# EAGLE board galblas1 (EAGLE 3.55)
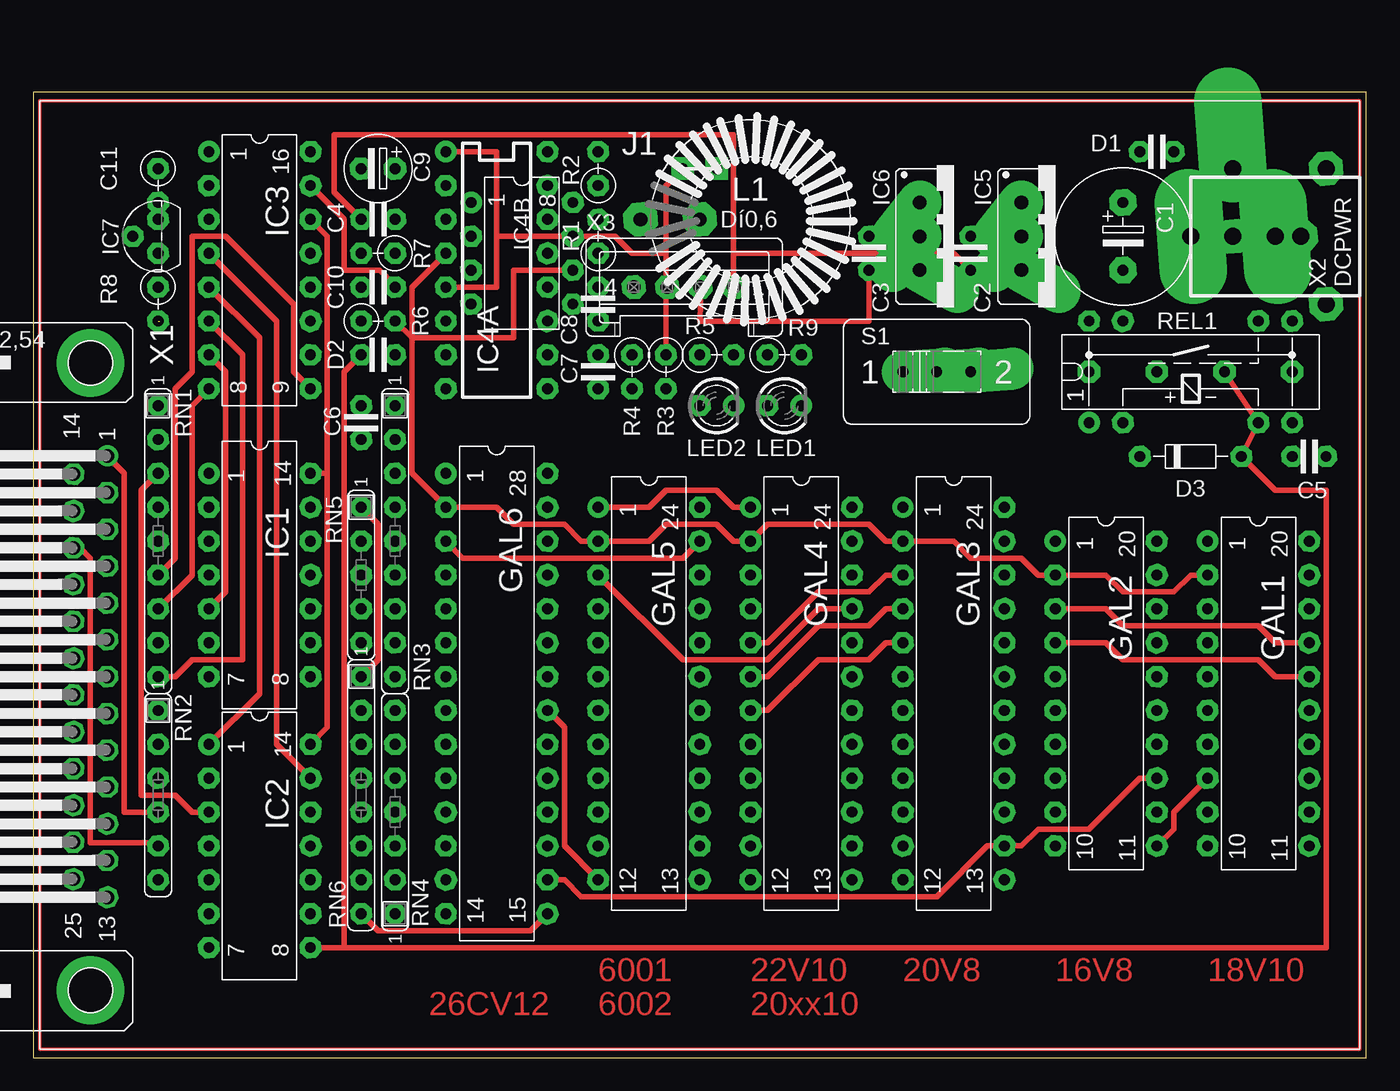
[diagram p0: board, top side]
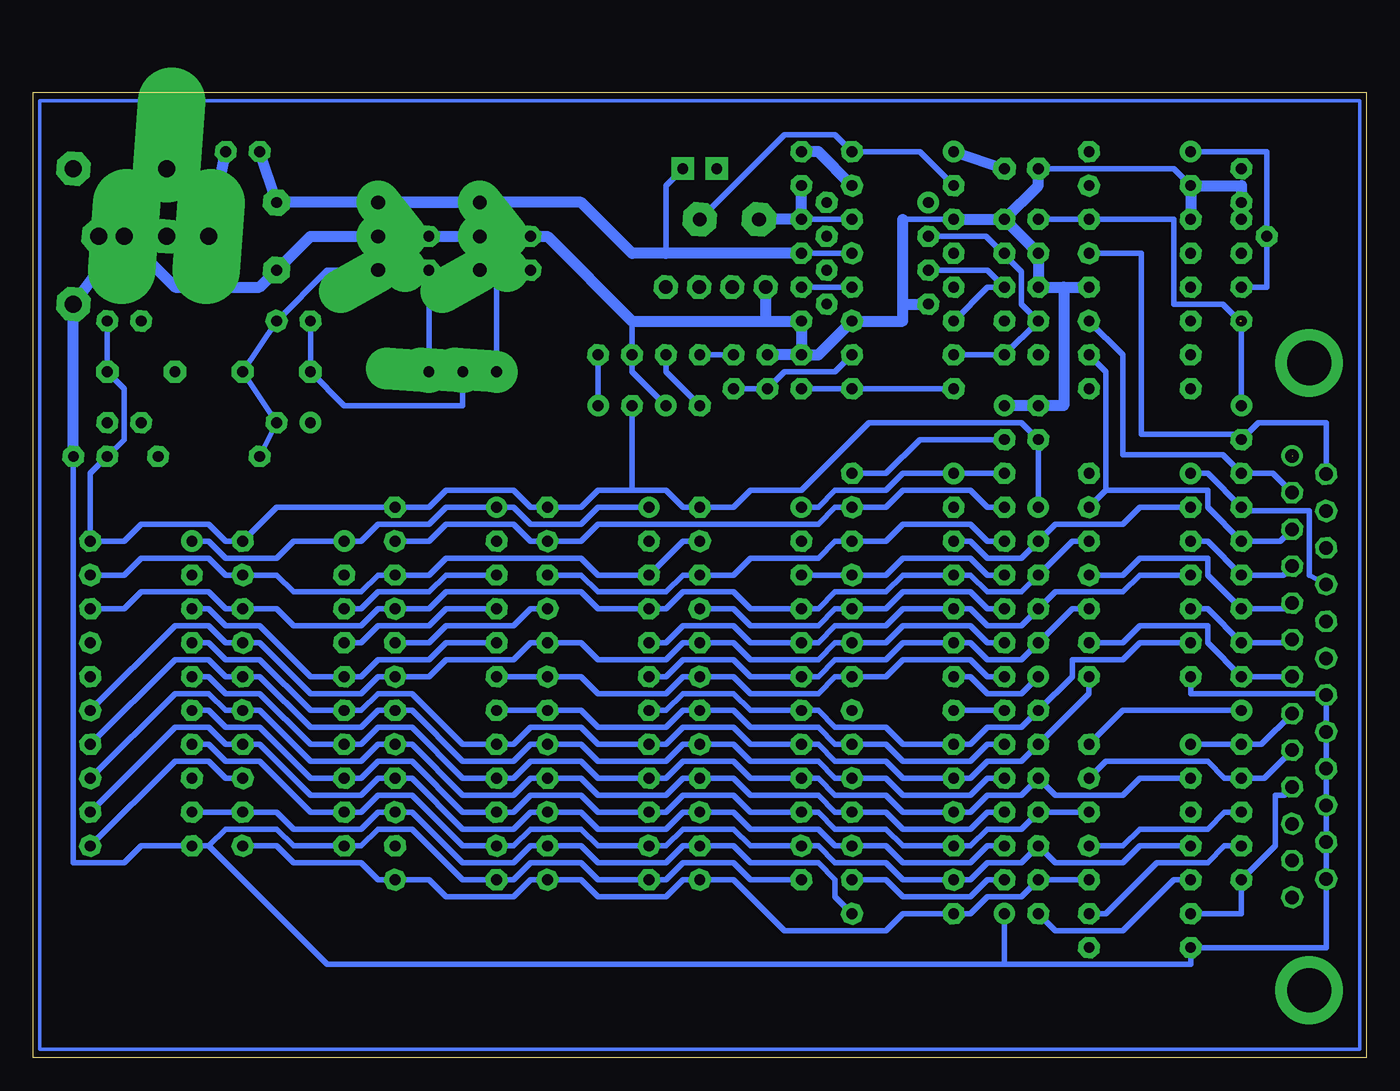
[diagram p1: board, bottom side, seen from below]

Size 100 x 72.38 mm. Coordinates in mm from the lower left corner, seen from the top.
Outline: 0,0 100,0 100,72.38 0,72.38 0,0
Copper layers used: Top, Bottom

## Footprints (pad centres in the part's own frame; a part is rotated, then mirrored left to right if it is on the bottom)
-5 = drill 0.813 pad 2.007 octagon:  -2.54,0;  2.54,0
2,5 = drill 0.813 pad 1.6 octagon:  -1.27,0;  1.27,0
-2,5L = drill 0.813 pad 1.676 octagon:  0,0;  2.54,0
-2,5 = drill 0.813 pad 1.6 octagon:  0,0;  2.54,0
7,5 = drill 0.813 pad 1.6 octagon:  -3.81,0;  3.81,0
L20 = drill 0.813 pad 1.6 round:  -11.43,-3.81 | drill 0.813 pad 1.6 octagon:  -8.89,-3.81;  -6.35,-3.81;  -3.81,-3.81;  -1.27,-3.81;  1.27,-3.81;  3.81,-3.81;  6.35,-3.81;  8.89,-3.81;  11.43,-3.81;  11.43,3.81;  8.89,3.81;  6.35,3.81;  3.81,3.81;  1.27,3.81;  -1.27,3.81;  -3.81,3.81;  -6.35,3.81;  -8.89,3.81;  -11.43,3.81
L24-3 = drill 0.813 pad 1.6 round:  -13.97,-3.81 | drill 0.813 pad 1.6 octagon:  -11.43,-3.81;  -8.89,-3.81;  -6.35,-3.81;  -3.81,-3.81;  -1.27,-3.81;  1.27,-3.81;  3.81,-3.81;  6.35,-3.81;  8.89,-3.81;  11.43,-3.81;  13.97,-3.81;  13.97,3.81;  11.43,3.81;  8.89,3.81;  6.35,3.81;  3.81,3.81;  1.27,3.81;  -1.27,3.81;  -3.81,3.81;  -6.35,3.81;  -8.89,3.81;  -11.43,3.81;  -13.97,3.81
L28-3 = drill 0.813 pad 1.6 round:  -16.51,-3.81 | drill 0.813 pad 1.6 octagon:  -13.97,-3.81;  -11.43,-3.81;  -8.89,-3.81;  -6.35,-3.81;  -3.81,-3.81;  -1.27,-3.81;  1.27,-3.81;  3.81,-3.81;  6.35,-3.81;  8.89,-3.81;  11.43,-3.81;  13.97,-3.81;  16.51,-3.81;  16.51,3.81;  13.97,3.81;  11.43,3.81;  8.89,3.81;  6.35,3.81;  3.81,3.81;  1.27,3.81;  -1.27,3.81;  -3.81,3.81;  -6.35,3.81;  -8.89,3.81;  -11.43,3.81;  -13.97,3.81;  -16.51,3.81
L14 = drill 0.813 pad 1.6 round:  -7.62,-3.81 | drill 0.813 pad 1.6 octagon:  -5.08,-3.81;  -2.54,-3.81;  0,-3.81;  2.54,-3.81;  5.08,-3.81;  7.62,-3.81;  7.62,3.81;  5.08,3.81;  2.54,3.81;  0,3.81;  -2.54,3.81;  -5.08,3.81;  -7.62,3.81
L16 = drill 0.813 pad 1.6 round:  -8.89,-3.81 | drill 0.813 pad 1.6 octagon:  -6.35,-3.81;  -3.81,-3.81;  -1.27,-3.81;  1.27,-3.81;  3.81,-3.81;  6.35,-3.81;  8.89,-3.81;  8.89,3.81;  6.35,3.81;  3.81,3.81;  1.27,3.81;  -1.27,3.81;  -3.81,3.81;  -6.35,3.81;  -8.89,3.81
L16' = drill 0.813 pad 1.6 round:  -8.89,-3.81 | drill 0.813 pad 1.6 octagon:  -6.35,-3.81;  -1.27,-3.81;  -3.81,-3.81;  1.27,-3.81;  3.81,-3.81;  6.35,-3.81;  8.89,-3.81;  8.89,3.81;  6.35,3.81;  3.81,3.81;  1.27,3.81;  -1.27,3.81;  -3.81,3.81;  -6.35,3.81;  -8.89,3.81
L08 = drill 0.813 pad 1.6 round:  -3.81,-3.81 | drill 0.813 pad 1.6 octagon:  -1.27,-3.81;  1.27,-3.81;  3.81,-3.81;  3.81,3.81;  1.27,3.81;  -1.27,3.81;  -3.81,3.81
XXS = drill 1.016 pad 3.251 offset:  -2.54,-2.54;  0,-2.54;  2.54,-2.54
92 = drill 0.813 pad 1.6 octagon:  -1.27,0;  0,1.905;  1.27,0
16 = drill 1.016 pad 2.54 octagon:  -3.81,0;  -8.255,0
D3 = drill 0.813 pad 1.6 octagon:  -1.27,0 | drill 0.813 pad 1.6 round:  1.27,0
1A = drill 0.813 pad 1.6 round:  -7.62,-3.81 | drill 0.813 pad 1.6 octagon:  -5.08,-3.81;  5.08,-3.81;  7.62,-3.81;  7.62,3.81;  5.08,3.81;  -5.08,3.81;  -7.62,3.81
L9 = drill 0.813 pad 1.6 round:  -10.16,0 | drill 0.813 pad 1.6 octagon:  -7.62,0;  -5.08,0;  -2.54,0;  0,0;  2.54,0;  5.08,0;  7.62,0;  10.16,0
L6 = drill 0.813 pad 1.6 round:  -6.35,0 | drill 0.813 pad 1.6 octagon:  -3.81,0;  -1.27,0;  1.27,0;  3.81,0;  6.35,0
L7 = drill 0.813 pad 1.6 round:  -7.62,0 | drill 0.813 pad 1.6 octagon:  -5.08,0;  -2.54,0;  0,0;  2.54,0;  5.08,0;  7.62,0
L5 = drill 0.813 pad 1.6 round:  -5.08,0 | drill 0.813 pad 1.6 octagon:  -2.54,0;  0,0;  2.54,0;  5.08,0
L8 = drill 0.813 pad 1.6 round:  -8.89,0 | drill 0.813 pad 1.6 octagon:  -6.35,0;  -3.81,0;  -1.27,0;  1.27,0;  3.81,0;  6.35,0;  8.89,0
51 = drill 0.813 pad 3.15 offset:  -2.54,0;  0,0;  2.54,0
5HP = drill 1.016 pad 1.6 octagon:  16.561,1.27;  13.792,1.27;  11.049,1.27;  8.28,1.27;  5.512,1.27;  2.769,1.27;  0,1.27;  -2.769,1.27;  -5.512,1.27;  -8.28,1.27;  -11.049,1.27;  -13.792,1.27;  15.189,-1.27;  12.421,-1.27;  9.652,-1.27;  6.909,-1.27;  4.14,-1.27;  1.372,-1.27;  -1.372,-1.27;  -4.14,-1.27;  -6.909,-1.27;  -9.652,-1.27;  -12.421,-1.27;  -15.189,-1.27 | drill 1.016 pad 1.6 round:  -16.561,1.27 | drill 3.302 pad 5.08 round:  -23.52,0;  23.52,0
PWR = drill 1.27 pad 2.54 octagon:  -5.08,-7.62;  5.08,-7.62;  0,-0.635;  0,-5.715 | drill 1.27 pad 5.08 offset:  5.08,-0.635 | drill 1.27 pad 5.08 long:  0,2.54;  0,-3.81
4P = drill 1.016 pad 1.778 octagon:  -4.978,0;  -7.493,0;  -2.489,0;  0,0

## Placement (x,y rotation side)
C1  470u/16V  [-5]  81.75,61.59 270 top
C2  100n  [2,5]  70.32,60.32 270 top
C3  100n  [2,5]  62.7,60.32 270 top
C4  100n  [2,5]  25.87,62.86 180 top
C5  100n  [2,5]  95.72,45.08 180 top
C6  100n  [2,5]  24.6,47.62 270 top
C7  100n  [2,5]  42.38,51.43 90 top
C8  10n  [2,5]  42.38,56.51 270 top
C9  100u/35V  [-2,5L]  27.14,66.67 180 top
C10  4n7  [2,5]  25.87,57.78 180 top
C11  1u/3V  [-2,5]  9.36,66.67 270 top
D1  1N4001  [2,5]  84.29,67.94 180 top
D2  1N4148  [2,5]  25.87,52.7 0 top
D3  1N4148  [7,5]  86.83,45.08 180 top
GAL1  18V10  [L20]  91.91,27.3 270 top
GAL2  16V8  [L20]  80.48,27.3 270 top
GAL3  20V8  [L24-3]  69.05,27.3 270 top
GAL4  22V10/20xx10  [L24-3]  57.62,27.3 270 top
GAL5  6001/6002  [L24-3]  46.19,27.3 270 top
GAL6  26CV12  [L28-3]  34.76,27.3 270 top
IC1  7417  [L14]  16.98,36.19 270 top
IC2  7417  [L14]  16.98,15.87 270 top
IC3  TLC7524JN  [L16]  16.98,59.05 270 top
IC4A  78S40  [L16']  34.76,59.05 270 top
IC4B  CA3140E  [L08]  36.66,60.32 270 top
IC5  7805  [XXS]  76.67,61.59 270 top
IC6  LM3940-3.3  [XXS]  69.05,61.59 270 top
IC7  LM336Z2.5  [92]  9.36,61.59 90 top
L1  470uH  [16]  53.81,62.86 0 top
LED1  LED3YE  [D3]  56.35,48.89 0 top
LED2  LED3GR  [D3]  51.27,48.89 0 top
R1  1R2  [-2,5]  42.38,60.32 90 top
R2  180R  [-2,5]  42.38,65.4 90 top
R3  220k  [-2,5]  47.46,52.7 270 top
R4  12k  [-2,5]  44.92,52.7 270 top
R5  4k7  [-2,5]  50,52.7 0 top
R6  100k  [-2,5]  24.6,55.24 0 top
R7  12k  [-2,5]  27.14,60.32 180 top
R8  390R  [-2,5]  9.36,57.78 270 top
R9  820R  [-2,5]  55.08,52.7 0 top
REL1  RR1A  [1A]  86.83,51.43 0 top
RN1  4k7  [L9]  9.36,38.73 270 top
RN2  4k7  [L6]  9.36,19.68 270 top
RN3  4k7  [L9]  27.14,38.73 270 top
RN4  4k7  [L7]  27.14,18.41 90 top
RN5  4k7  [L5]  24.6,36.19 270 top
RN6  4k7  [L8]  24.6,19.68 270 top
S1  SW1  [51]  67.78,51.43 0 top
X1  M25HP  [5HP]  4.28,28.57 270 top
X2  DCPWR  [PWR]  89.37,61.59 90 top
X3  S04P  [4P]  52.54,57.78 0 top

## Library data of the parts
C1-C11 D1-D3 R1-R9 = DISCRETE
GAL1-GAL6 = DIL
IC1 IC2 = 74XX
IC3 IC4B IC7 = LINEAR
IC4A IC5 IC6 = V-REG
L1 = IND-A
LED1 LED2 = LED
REL1 = RELAIS
RN1-RN6 = R-SIL
S1 = SWITCH
X1 = SUBD-A
X2 = SPECIAL
X3 = CON-MT

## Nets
/ACK: IC2. RN2. X1.
/STB: GAL1. GAL2. GAL3. GAL4. GAL5. GAL6. IC2. RN6.
/STROBE: IC2. RN2. X1.
D0: IC2. IC3. RN1. X1.
D1: IC1. IC3. RN1. X1.
D2: IC1. IC3. RN1. X1.
D3: IC1. IC3. RN1. X1.
D4: IC1. IC3. RN1. X1.
D5: IC1. IC3. RN1. X1.
D6: IC2. IC3. RN2. X1.
D7: IC2. IC3. RN2. X1.
EDIT: GAL1. GAL2. GAL3. GAL4. GAL5. GAL6. IC4A. IC4B. R6.
N$1: IC3. RN1. X1.
N$2: D1. X2.
N$3: IC1. RN1. X1.
N$4: IC2. RN2. X1.
N$5: C7. IC4A.
N$6: LED2. R5.
N$7: C8. IC4A.
N$8: REL1. S1.
N$9: GAL6. RN4.
N$10: GAL3. GAL4. GAL5. GAL6. RN3.
N$11: IC4A. R3. R4.
N$12: LED1. R9.
N$13: IC4A. L1. R1. R2.
N$14: IC4A. R2.
N$15: GAL5. GAL6. RN3.
N$16: GAL1. GAL2. GAL3. GAL4. GAL5. GAL6. RN3.
N$17: IC4A. L1.
N$18: C9. IC4A. IC4B. R3. R5. X3.
N$19: C1. C2. C3. C4. C5. C6. C7. C8. C9. C10. C11. GAL1. GAL2. GAL3. GAL4. GAL5. GAL6. IC1. IC2. IC3. IC4A. IC4B. IC5. IC6. IC7. LED2. R4. R7. R9. RN3. RN4. X1. X2. X3.
N$20: C1. D1. IC4A. IC5. IC6. R1.
N$21: C11. IC3. IC7. R8.
N$22: GAL3. GAL4. GAL5. GAL6. RN3.
N$23: D2. IC4A. IC4B. R6. R7.
N$24: GAL3. GAL4. GAL5. GAL6. RN4.
N$25: GAL1. GAL2. GAL3. GAL4. GAL5. GAL6. RN4.
N$26: GAL1. GAL2. GAL3. GAL4. GAL5. GAL6. RN4.
N$28: GAL1. GAL2. GAL3. GAL4. GAL5. GAL6. RN4.
N$29: GAL1. GAL2. GAL3. GAL6. RN4.
N$30: GAL6. RN3.
N$31: GAL1. GAL2. GAL3. GAL4. GAL5. GAL6. RN3.
N$32: GAL4. GAL5. GAL6. RN3.
N$33: GAL3. GAL4. GAL6. RN3.
N$35: C10. IC3. IC4A. IC4B.
N$36: C2. C4. D3. IC1. IC2. IC3. IC5. R8. REL1. RN1. RN2. S1. X3.
N$39: D2. D3. IC2. REL1.
P/V: GAL1. GAL2. GAL3. GAL4. GAL5. GAL6. IC1. RN5.
RA0: GAL1. GAL2. GAL3. GAL4. GAL5. GAL6. IC1. RN5.
RA1: GAL1. GAL2. GAL3. GAL4. GAL5. GAL6. IC1. RN5.
RA2: GAL1. GAL2. GAL3. GAL4. GAL5. GAL6. IC1. RN5.
RA3: GAL1. GAL2. GAL3. GAL4. GAL5. GAL6. IC1. RN6.
RA4: GAL1. GAL2. GAL3. GAL4. GAL5. GAL6. IC1. RN6.
RA5: GAL1. GAL2. GAL3. GAL4. GAL5. GAL6. IC2. RN6.
SCHALT: X2.
SCLK: GAL1. GAL2. GAL3. GAL4. GAL5. GAL6. IC2. RN6.
SDIN: GAL1. GAL2. GAL3. GAL4. GAL5. GAL6. IC2. RN6.
SDOUT: GAL1. GAL2. GAL3. GAL4. GAL5. GAL6. IC2. RN6.
SW1: C3. IC6. S1. X3.
VCC: C5. C6. GAL1. GAL2. GAL3. GAL4. GAL5. GAL6. LED1. REL1. RN5. RN6.

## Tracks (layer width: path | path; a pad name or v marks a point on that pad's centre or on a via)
/ACK
  Bottom 0.406: 5.55,20.29 6.16,19.68 6.82,19.68 6.82,15.87 RN2. 9.36,10.79 13.17,10.79
/STB
  Top 0.406: 88.1,20.95 85.56,18.41 85.56,17.14 84.29,15.87
  Bottom 0.406: 84.29,15.87 81.75,15.87 80.48,14.6 75.4,14.6 74.13,13.33 72.86,13.33 70.32,13.33 69.05,12.06 63.97,12.06 62.7,13.33 61.43,13.33 58.89,13.33 57.62,12.06 52.54,12.06 51.27,13.33 50,13.33 47.46,13.33 43.65,9.52 36.03,9.52 34.76,10.79 30.95,10.79 29.68,10.79 28.41,12.06 25.87,12.06 24.6,13.33 20.79,13.33
/STROBE  (1 unrouted)
  Top 0.406: 5.55,45.08 6.82,43.81 6.82,18.41 9.36,18.41
  Bottom 0.406: 9.36,18.41 10.63,18.41 11.9,17.14 16.98,17.14 18.25,15.87 20.79,15.87
D0
  Top 0.406: 9.36,43.81 8.09,42.54 8.09,19.68 10.63,19.68 11.9,18.41 13.17,18.41
  Bottom 0.406: 5.55,42.36 7,43.81 9.36,43.81 10.76,45.21 18.25,45.21 18.25,52.7 20.79,55.24
D1
  Bottom 0.406: 5.55,39.62 6.44,38.73 9.36,38.73 11.9,41.27 11.9,42.54 19.52,42.54 | 19.52,42.54 20.79,41.27 | 19.52,42.54 19.52,51.43 20.79,52.7
D2
  Top 0.406: 20.79,50.16 19.52,51.43 19.52,56.51 14.44,61.59 11.9,61.59 11.9,51.43 10.63,50.16 10.63,37.46 9.36,36.19
  Bottom 0.406: 5.55,36.85 6.21,36.19 9.36,36.19 11.9,38.73 13.17,38.73
D3
  Top 0.406: 13.17,50.16 11.9,48.89 11.9,36.19 9.36,33.65
  Bottom 0.406: 5.55,34.08 5.98,33.65 9.36,33.65 11.9,36.19 11.9,37.46 16.98,37.46 18.25,36.19 20.79,36.19
D4
  Top 0.406: 13.17,52.7 14.44,51.43 14.44,34.92 13.17,33.65
  Bottom 0.406: 5.55,31.34 5.78,31.11 9.36,31.11 11.9,33.65 13.17,33.65
D5
  Top 0.406: 13.17,55.24 15.71,52.7 15.71,29.84 11.9,29.84 10.63,28.57 RN1.
  Bottom 0.406: 5.55,28.57 RN1. 11.9,31.11 11.9,32.38 16.98,32.38 18.25,31.11 20.79,31.11
D6
  Top 0.406: 13.17,57.78 16.98,53.97 16.98,27.3 13.17,23.49
  Bottom 0.406: 5.55,25.8 7.86,23.49 9.36,23.49 13.17,23.49
D7
  Top 0.406: 13.17,60.32 18.25,55.24 18.25,23.49 20.79,20.95
  Bottom 0.406: 5.55,23.06 7.66,20.95 9.36,20.95 10.63,20.95 11.9,22.22 19.52,22.22 20.79,20.95
EDIT
  Top 0.406: 88.1,36.19 86.83,36.19 85.56,34.92 81.75,34.92 80.48,36.19 76.67,36.19 75.4,36.19 74.13,37.46 70.32,37.46 69.05,38.73 65.24,38.73 63.97,38.73 62.7,40 55.08,40 53.81,38.73 52.54,38.73 51.27,40 47.46,40 46.19,38.73 42.38,38.73 41.11,38.73 39.84,40 36.03,40 34.76,41.27 30.95,41.27 28.41,43.81 28.41,53.97 | 40.48,59.05 36.03,59.05 36.03,53.97 28.41,53.97 | 28.41,53.97 R6. | 30.95,60.32 28.41,57.78 28.41,53.97
N$1
  Bottom 0.406: 3.01,43.76 3.01,47.62 8.09,47.62 9.36,46.35 9.74,46.73 16.85,46.73 16.85,60.32 20.79,60.32
N$2
  Bottom 0.813: 85.56,67.94 86.83,61.59 89.37,61.59
N$3
  Bottom 0.406: 3.01,35.48 4.28,36.19 4.28,41.02 9.11,41.02 9.36,41.27 11.9,43.81 13.17,43.81
N$4
  Top 0.406: 3.01,38.22 3.52,38.22 4.28,37.46 4.28,16.12 9.11,16.12 9.36,15.87
  Bottom 0.406: 9.36,15.87 10.63,15.87 11.9,14.6 15.71,14.6 19.52,10.79 20.79,10.79
N$5
  Bottom 0.406: 30.95,50.16 38.57,50.16 42.38,50.16
N$6
  Bottom 0.406: 50,48.89 52.54,51.43 R5.
N$7
  Bottom 0.406: 38.57,57.78 42.38,57.78
N$8  (via drill 0.81 pad 1.68)
  Bottom 0.406: 67.78,51.43 67.78,48.89 76.67,48.89 v79.21,51.43 REL1.
N$9
  Bottom 0.406: RN4. 30.95,26.03
N$10
  Top 0.406: 61.43,33.65 58.89,33.65 55.08,29.84 48.73,29.84 42.38,36.19
  Bottom 0.406: 42.38,36.19 38.57,36.19 36.03,36.19 34.76,37.46 29.68,37.46 28.41,36.19 27.14,36.19 | 61.43,33.65 62.7,33.65 63.97,32.38 69.05,32.38 70.32,31.11 72.86,31.11
N$11
  Bottom 0.406: 38.57,52.7 39.84,51.43 43.65,51.43 R4. R3.
N$12
  Bottom 0.406: LED1. R9.
N$13
  Bottom 0.406: 38.57,62.86 R1.
  Bottom 0.813: 42.38,65.4 R1. L1.
N$14
  Bottom 0.813: 38.57,65.4 41.11,67.94 R2.
N$15
  Bottom 0.406: 50,33.65 47.46,33.65 46.19,32.38 41.11,32.38 39.84,33.65 38.57,33.65 36.03,33.65 34.76,34.92 29.68,34.92 28.41,33.65 27.14,33.65
N$16
  Bottom 0.406: 27.14,31.11 28.41,31.11 29.68,32.38 34.76,32.38 36.03,31.11 38.57,31.11 39.84,31.11 41.11,29.84 46.19,29.84 47.46,31.11 50,31.11 51.27,31.11 52.54,29.84 57.62,29.84 58.89,31.11 61.43,31.11 62.7,31.11 63.97,29.84 69.05,29.84 70.32,28.57 72.86,28.57 74.13,28.57 75.4,27.3 79.21,27.3 83.02,31.11 84.29,31.11 85.56,31.11 86.83,32.38 89.37,32.38 95.72,26.03
N$17
  Bottom 0.406: 30.95,65.4 33.49,67.94 IC4A. 39.84,69.21 43.65,69.21 50,62.86
N$18  (via drill 0.81 pad 1.68)
  Top 0.406: 47.46,57.78 47.46,52.7 | 47.46,57.78 47.56,57.78 | 47.46,60.32 47.46,57.78 | 47.46,60.32 44.92,60.32 43.65,61.59 40.48,61.59 34.76,61.59 | 34.76,61.59 34.76,67.94 30.95,67.94 | 47.46,60.32 47.46,65.4 v48.73,66.67 | 30.95,57.78 34.76,57.78 34.76,61.59
  Bottom 0.406: 47.46,52.7 50,52.7
  Bottom 0.813: 30.95,67.94 27.14,66.67
N$19
  Top 0.406: 38.57,26.03 39.84,24.76 39.84,15.87 42.38,13.33
  Bottom 0.406: 42.38,13.33 46.19,13.33 47.46,14.6 51.27,14.6 52.54,13.33 53.81,13.33 57.62,13.33 58.89,14.6 62.7,14.6 63.97,13.33 65.24,13.33 67.78,13.33 71.59,17.14 74.13,17.14 75.4,15.87 76.67,15.87 80.48,15.87 81.75,17.14 85.56,17.14 86.83,15.87 | 24.6,48.89 27.14,48.89 | 86.83,15.87 88.1,15.87 91.91,15.87 93.18,14.6 96.99,14.6 96.99,45.08 | 27.14,6.98 13.17,6.98 13.17,8.25 3.01,8.25 3.01,13.38 3.01,16.15 3.01,18.41 | 13.17,28.57 13.17,27.3 3.01,27.3 3.01,27.2 3.01,24.43 3.01,21.66 | 27.14,6.98 27.14,10.79 | 27.14,6.98 77.94,6.98 86.83,15.87 | 34.76,62.86 30.95,62.86 | 55.08,55.24 55.08,52.7 55.08,51.43 LED2. | 3.01,18.41 3.01,18.92 3.01,20.95 | 3.01,21.66 3.01,22.22 | 3.01,20.95 3.01,21.66 | 3.01,18.41 3.01,20.95 | 3.01,18.41 3.01,21.66 | 13.17,65.4 14.44,66.67 C9. | C8. C7. C8.
  Bottom 0.813: 70.32,61.59 62.7,61.59 66.51,61.59 70.32,61.59 | 70.32,61.59 74.13,61.59 70.32,61.59 | 70.32,61.59 79.21,61.59 C1. 83.02,57.78 89.37,57.78 93.18,61.59 96.99,56.51 96.99,45.08 | C7. 41.11,52.7 38.57,55.24 34.76,55.24 34.76,56.51 | 34.76,56.51 34.76,62.86 | C7. C8. 44.92,55.24 | C7. 44.92,52.7 | 27.14,48.89 24.6,48.89 22.7,48.89 22.7,57.78 | 70.32,61.59 61.43,61.59 55.08,55.24 44.92,55.24 | 45.05,57.78 45.05,55.37 44.92,55.24 | 13.17,62.86 13.17,65.4 9.36,65.4 IC7. | 34.76,56.51 32.85,56.51 | 30.95,62.86 27.14,62.86 | 22.7,57.78 C10. R7. 27.14,62.86 | 27.14,62.86 24.6,65.4 C9. | 22.7,57.78 20.79,57.78
N$20  (via drill 0.81 pad 1.68)
  Bottom 0.406: 38.57,60.32 42.38,60.32 | 52.54,60.32 52.54,65.4 v51.27,66.67
  Bottom 0.813: 42.38,60.32 52.54,60.32 55.08,60.32 58.89,64.13 74.13,64.13 66.51,64.13 81.75,64.13 D1.
N$21
  Bottom 0.406: 13.17,67.94 9.36,67.94 7.46,67.94 7.46,61.59 7.46,57.78 9.36,57.78
N$22
  Bottom 0.406: 65.24,28.57 61.43,28.57 58.89,28.57 57.62,27.3 52.54,27.3 51.27,28.57 50,28.57 47.46,28.57 46.19,27.3 41.11,27.3 39.84,28.57 38.57,28.57 36.03,28.57 34.76,29.84 29.68,29.84 28.41,28.57 RN3.
N$23
  Bottom 0.406: 30.95,52.7 D2. 24.6,55.24 25.87,56.51 25.87,58.92 27.14,60.19 | 27.14,60.19 27.14,60.32 | 32.85,61.59 28.54,61.59 27.14,60.19
N$24
  Bottom 0.406: 65.24,26.03 61.43,26.03 58.89,26.03 57.62,24.76 52.54,24.76 51.27,26.03 50,26.03 47.46,26.03 46.19,24.76 41.11,24.76 39.84,23.49 38.57,23.49 36.03,23.49 34.76,22.22 29.68,22.22 28.41,23.49 27.14,23.49
N$25
  Bottom 0.406: 27.14,20.95 28.41,20.95 29.68,19.68 34.76,19.68 36.03,20.95 38.57,20.95 39.84,20.95 41.11,22.22 46.19,22.22 47.46,23.49 50,23.49 51.27,23.49 52.54,22.22 57.62,22.22 58.89,23.49 61.43,23.49 62.7,23.49 63.97,22.22 67.78,22.22 71.59,26.03 72.86,26.03 74.13,26.03 75.4,24.76 79.21,24.76 83.02,28.57 84.29,28.57 85.56,28.57 86.83,29.84 89.37,29.84 95.72,23.49
N$26
  Bottom 0.406: 27.14,18.41 28.41,18.41 29.68,17.14 34.76,17.14 36.03,18.41 38.57,18.41 39.84,18.41 41.11,19.68 46.19,19.68 47.46,20.95 50,20.95 51.27,20.95 52.54,19.68 57.62,19.68 58.89,20.95 61.43,20.95 62.7,20.95 63.97,19.68 67.78,19.68 71.59,23.49 72.86,23.49 74.13,23.49 75.4,22.22 79.21,22.22 83.02,26.03 84.29,26.03 85.56,26.03 86.83,27.3 89.37,27.3 95.72,20.95
N$28
  Bottom 0.406: 27.14,15.87 28.41,15.87 29.68,14.6 34.76,14.6 36.03,15.87 38.57,15.87 39.84,15.87 41.11,17.14 46.19,17.14 47.46,18.41 50,18.41 51.27,18.41 52.54,17.14 57.62,17.14 58.89,18.41 61.43,18.41 62.7,18.41 63.97,17.14 67.78,17.14 71.59,20.95 72.86,20.95 74.13,20.95 75.4,19.68 79.21,19.68 83.02,23.49 84.29,23.49 85.56,23.49 86.83,24.76 89.37,24.76 95.72,18.41
N$29
  Top 0.406: 38.57,13.33 39.84,13.33 41.11,12.06 67.78,12.06 71.59,15.87 72.86,15.87 74.13,15.87 75.4,17.14 79.21,17.14 83.02,20.95 84.29,20.95
  Bottom 0.406: 38.57,13.33 36.03,13.33 34.76,12.06 29.68,12.06 28.41,13.33 27.14,13.33 | 95.72,15.87 89.37,22.22 86.83,22.22 85.56,20.95 84.29,20.95
N$30
  Bottom 0.406: GAL6. 36.03,43.81 33.49,46.35 27.14,46.35
N$31
  Top 0.406: 42.38,41.27 46.19,41.27 47.46,42.54 51.27,42.54 52.54,41.27 53.81,41.27
  Bottom 0.406: 42.38,41.27 41.11,41.27 39.84,42.54 36.03,42.54 34.76,43.81 30.95,43.81 27.14,43.81 | 88.1,38.73 86.83,38.73 85.56,37.46 81.75,37.46 80.48,38.73 76.67,38.73 75.4,38.73 74.13,40 70.32,40 69.05,41.27 65.24,41.27 63.97,41.27 62.7,40 58.89,40 57.62,41.27 53.81,41.27
N$32
  Bottom 0.406: 61.43,36.19 58.89,36.19 57.62,34.92 52.54,34.92 51.27,36.19 50,36.19 47.46,36.19 46.19,37.46 41.11,37.46 39.84,38.73 38.57,38.73 36.03,38.73 34.76,40 29.68,40 28.41,38.73 27.14,38.73
N$33
  Bottom 0.406: 72.86,38.73 70.32,38.73 69.05,40 63.97,40 62.7,38.73 61.43,38.73 58.89,38.73 57.62,40 41.11,40 39.84,41.27 38.57,41.27 36.03,41.27 34.76,42.54 29.68,42.54 28.41,41.27 27.14,41.27
N$34
  Top 0.254: 0.47,71.75 99.53,71.75 99.53,0.63 0.47,0.63 0.47,71.75
N$35
  Top 0.406: 20.79,65.4 23.33,62.86 23.33,59.05 26,59.05 26.38,58.67 27.14,57.78
  Bottom 0.406: 32.85,59.05 28.41,59.05 27.14,57.78 28.41,57.78 30.95,55.24
N$36  (via drill 0.81 pad 1.68)  (1 unrouted)
  Top 0.406: C4. 22.57,64.89 22.57,69.21 52.54,69.21 52.54,60.32 | 52.54,60.32 X3. | C2. 69.05,60.32 52.54,60.32 | 22.06,43.81 22.06,24.76 IC2. | 22.06,43.81 IC1. | 22.06,43.81 22.06,61.59 20.79,62.86
  Bottom 0.406: 9.49,55.24 10.76,56.51 14.44,56.51 14.44,62.86 20.79,62.86 C4. | IC2. 18.25,26.03 9.36,26.03 | C2. IC5. | C2. S1. | C2. IC5. | D3. 81.75,47.62 v84.29,51.43 81.75,55.24 77.94,59.05 IC5. | 9.36,48.89 R8.
N$37
  Bottom 0.254: 0.47,71.75 99.53,71.75 99.53,0.63 0.47,0.63 0.47,71.75
N$38  (via drill 0.81 pad 1.68)
  other vias: 94.45,51.43
N$39  (via drill 0.81 pad 1.68)
  Top 0.406: 20.79,8.25 23.33,8.25 | 23.33,8.25 23.33,51.43 24.6,52.7 | 23.33,8.25 96.99,8.25 96.99,42.54 93.18,42.54 90.64,45.08 91.91,47.62 v89.37,51.43
P/V
  Top 0.406: 50,38.73 48.73,37.46 32.22,37.46 30.95,38.73
  Bottom 0.406: 50,38.73 51.27,38.73 53.81,36.19 57.62,36.19 58.89,37.46 69.05,37.46 70.32,36.19 72.86,36.19 74.13,36.19 75.4,34.92 80.48,34.92 81.75,36.19 84.29,36.19 85.56,36.19 86.83,37.46 91.91,37.46 93.18,36.19 95.72,36.19 | 30.95,38.73 29.68,38.73 28.41,37.46 25.87,37.46 24.6,38.73 23.33,40 18.25,40 16.98,41.27 13.17,41.27
RA0
  Bottom 0.406: 95.72,33.65 93.18,33.65 91.91,34.92 86.83,34.92 85.56,33.65 84.29,33.65 81.75,33.65 80.48,32.38 75.4,32.38 74.13,33.65 72.86,33.65 70.32,33.65 69.05,34.92 58.89,34.92 57.62,33.65 53.81,33.65 52.54,33.65 51.27,34.92 47.46,34.92 46.19,33.65 42.38,33.65 41.11,33.65 39.84,34.92 36.03,34.92 34.76,36.19 30.95,36.19 29.68,36.19 28.41,34.92 25.87,34.92 24.6,36.19 22.06,38.73 20.79,38.73
RA1
  Top 0.406: 76.67,33.65 80.48,33.65 81.75,32.38 91.91,32.38 93.18,31.11 95.72,31.11 | 53.81,31.11 55.08,31.11 58.89,34.92 62.7,34.92 63.97,36.19 65.24,36.19
  Bottom 0.406: 53.81,31.11 52.54,31.11 51.27,32.38 47.46,32.38 46.19,31.11 42.38,31.11 41.11,31.11 39.84,32.38 36.03,32.38 34.76,33.65 30.95,33.65 29.68,33.65 28.41,32.38 25.87,32.38 24.6,33.65 23.33,34.92 18.25,34.92 16.98,36.19 13.17,36.19 | 65.24,36.19 69.05,36.19 70.32,34.92 74.13,34.92 75.4,33.65 76.67,33.65
RA2
  Top 0.406: 76.67,31.11 80.48,31.11 81.75,29.84 91.91,29.84 93.18,28.57 95.72,28.57 | 53.81,28.57 55.08,28.57 58.89,32.38 62.7,32.38 63.97,33.65 65.24,33.65
  Bottom 0.406: 53.81,28.57 52.54,28.57 51.27,29.84 47.46,29.84 46.19,28.57 42.38,28.57 41.11,28.57 39.84,29.84 36.03,29.84 34.76,31.11 30.95,31.11 29.68,31.11 28.41,29.84 25.87,29.84 RN5. 22.06,33.65 20.79,33.65 | 65.24,33.65 69.05,33.65 70.32,32.38 74.13,32.38 75.4,31.11 76.67,31.11
RA3
  Top 0.406: 53.81,26.03 55.08,26.03 58.89,29.84 62.7,29.84 63.97,31.11 65.24,31.11
  Bottom 0.406: 53.81,26.03 52.54,26.03 51.27,27.3 47.46,27.3 46.19,26.03 42.38,26.03 41.11,26.03 39.84,24.76 36.03,24.76 34.76,23.49 30.95,23.49 29.68,23.49 28.41,24.76 25.87,24.76 24.6,26.03 22.06,28.57 22.06,29.84 18.25,29.84 16.98,31.11 13.17,31.11 | 88.1,33.65 86.83,33.65 85.56,32.38 83.02,32.38 79.21,28.57 76.67,28.57 75.4,28.57 74.13,29.84 70.32,29.84 69.05,31.11 65.24,31.11
RA4
  Bottom 0.406: 88.1,31.11 86.83,31.11 85.56,29.84 83.02,29.84 79.21,26.03 76.67,26.03 75.4,26.03 74.13,27.3 71.59,27.3 67.78,23.49 65.24,23.49 63.97,23.49 62.7,24.76 58.89,24.76 57.62,23.49 53.81,23.49 52.54,23.49 51.27,24.76 47.46,24.76 46.19,23.49 42.38,23.49 41.11,23.49 39.84,22.22 36.03,22.22 34.76,20.95 30.95,20.95 29.68,20.95 28.41,22.22 25.87,22.22 24.6,23.49 20.79,27.3 20.79,28.57
RA5
  Bottom 0.406: 88.1,28.57 86.83,28.57 85.56,27.3 83.02,27.3 79.21,23.49 76.67,23.49 75.4,23.49 74.13,24.76 71.59,24.76 67.78,20.95 65.24,20.95 63.97,20.95 62.7,22.22 58.89,22.22 57.62,20.95 53.81,20.95 52.54,20.95 51.27,22.22 47.46,22.22 46.19,20.95 42.38,20.95 41.11,20.95 39.84,19.68 36.03,19.68 34.76,18.41 30.95,18.41 29.68,18.41 28.41,19.68 25.87,19.68 24.6,20.95 23.33,19.68 18.25,19.68 16.98,20.95 13.17,20.95
SCLK
  Bottom 0.406: 88.1,26.03 86.83,26.03 85.56,24.76 83.02,24.76 79.21,20.95 76.67,20.95 75.4,20.95 74.13,22.22 71.59,22.22 67.78,18.41 65.24,18.41 63.97,18.41 62.7,19.68 58.89,19.68 57.62,18.41 53.81,18.41 52.54,18.41 51.27,19.68 47.46,19.68 46.19,18.41 42.38,18.41 41.11,18.41 39.84,17.14 36.03,17.14 34.76,15.87 30.95,15.87 29.68,15.87 28.41,17.14 25.87,17.14 24.6,18.41 20.79,18.41
SDIN
  Bottom 0.406: 88.1,23.49 86.83,23.49 85.56,22.22 83.02,22.22 79.21,18.41 76.67,18.41 75.4,18.41 74.13,19.68 71.59,19.68 67.78,15.87 65.24,15.87 63.97,15.87 62.7,17.14 58.89,17.14 57.62,15.87 53.81,15.87 52.54,15.87 51.27,17.14 47.46,17.14 46.19,15.87 42.38,15.87 41.11,15.87 39.84,14.6 36.03,14.6 34.76,13.33 30.95,13.33 29.68,13.33 28.41,14.6 25.87,14.6 24.6,15.87 23.33,14.6 18.25,14.6 16.98,15.87 13.17,15.87
SDOUT
  Top 0.406: RN6. 25.87,9.52 37.3,9.52 38.57,10.79
  Bottom 0.406: 88.1,18.41 84.29,18.41 81.75,18.41 80.48,17.14 75.4,17.14 74.13,18.41 72.86,18.41 71.59,18.41 67.78,14.6 63.97,14.6 62.7,15.87 61.43,15.87 58.89,15.87 57.62,14.6 52.54,14.6 51.27,15.87 50,15.87 47.46,15.87 46.19,14.6 41.11,14.6 39.84,13.33 39.84,12.06 38.57,10.79 | 13.17,13.33 14.44,13.33 18.25,9.52 23.33,9.52 RN6.
SW1
  Top 0.406: 50.05,57.78 50.05,56.56 50,55.24 62.7,55.24 C3.
  Bottom 0.406: C3. IC6. 65.24,59.05 65.24,51.43
VCC
  Top 0.406: 24.6,28.57 25.87,29.84 25.87,40 24.6,41.27
  Bottom 0.406: 55.08,42.54 52.54,42.54 51.27,41.27 GAL5. 47.46,41.27 46.19,42.54 42.38,42.54 37.3,47.62 25.87,47.62 C6. 24.6,41.27 | 55.08,42.54 57.62,42.54 58.89,41.27 GAL4. 62.7,41.27 63.97,42.54 69.05,42.54 70.32,41.27 GAL3. 81.75,41.27 GAL2. 85.56,38.73 86.83,40 91.91,40 93.18,38.73 GAL1. 95.72,43.81 C5. 93.18,46.35 93.18,50.16 94.45,51.43 94.45,55.24 | 24.6,28.57 25.87,27.3 28.41,27.3 29.68,28.57 30.95,28.57 | 55.08,42.54 55.08,48.89

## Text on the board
Top: 6001 | 22V10 | 20V8 | 16V8 | 18V10 | 26CV12 | 6002 | 20xx10
tPlace: J1
tDocu: 6001 | 22V10 | 20V8 | 16V8 | 18V10 | 26CV12 | 6002 | 20xx10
